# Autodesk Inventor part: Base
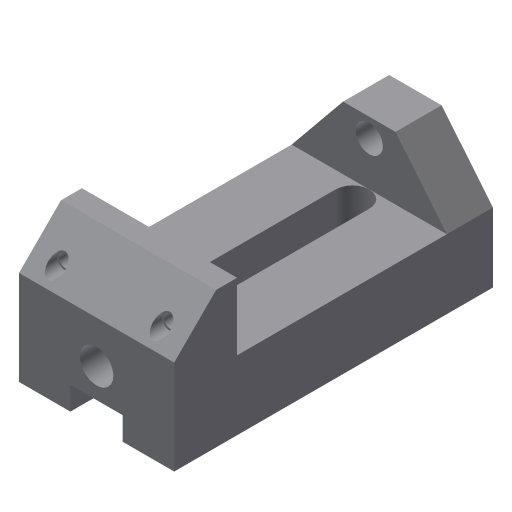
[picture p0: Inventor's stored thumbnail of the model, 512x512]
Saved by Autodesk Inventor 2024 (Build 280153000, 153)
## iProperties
Shininess: 77.0
Length Units: 11269
Angle Units: 11279
Time Units: 11290
Mass Units: 11283
Length Display Precision: 3
Angle Display Precision: 2
Created: 2002-02
Part Number: Base
Document SubType Name: Modeling
Designer: ***
Density: 1 g/cm^3
Material: Generic
Appearance: Default
Density: 0.0
Volumn: 0.0
Area: 0.0
PropertySet Name: Model Information
Control State: 0
Master: False
Checked Out: False
Author: ***
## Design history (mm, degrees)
sketch "Sketch2"
  geometry: L1 (-63.961, -4.254)-(-63.961, -37.254); L2 (-63.961, -37.254)-(88.039, -37.254); L3 (88.039, -37.254)-(88.039, 7.746); L4 (88.039, 7.746)-(68.039, 27.746); L5 (68.039, 27.746)-(58.039, 27.746); L6 (58.039, 27.746)-(58.039, -4.254); L7 (58.039, -4.254)-(-63.961, -4.254)
  constraints: 14 end point, 4 parallel, 1 perpendicular, 1 vertical
  dimensions: "d7" = 10 distance of L4.end L5.end; "d8" = 135 deg angle of L3 L4; "d9" = 33 distance of L1.start L1.end; "d10" = 152 distance of L1.end L2.end; "d11" = 65 distance between parallel lines of L5 L2; "d21" = 30 distance between parallel lines of L3 L6
extrude "Extrusion1" new body sketch "Sketch2" stored distance "d13" = 74; taper "d14" = 0 deg
sketch "Sketch3"
  geometry: L1 (0, 74)-(0, 0) reference; L2 (0, 0)-(-30, 24.5); L3 (-30, 24.5)-(-30, 49.5); L4 (-30, 49.5)-(0, 74); C1 r 6.5 at (-21, 37)
  constraints: 6 end point, 1 centre point, 1 equal length, 1 parallel
  dimensions: "d15" = 25 distance of L2.end L3.end; "d16" = 30 distance between parallel lines of L3 L1; "d17" = 13 diameter of C1; "d18" = 9 distance from line of L3 C1.centre
extrude "Extrusion2" join sketch "Sketch3" distance "d19" = 22; taper "d20" = 0 deg
sketch "Sketch4"
  geometry: L1 (0, 0)-(0, 74) reference; L2 (0, 0)-(45, 0) reference; C1 r 8 at (25, 37)
  constraints: 1 centre point
  dimensions: "d22" = 16 diameter of C1; "d23" = 25 distance from line of L1 C1.centre; "d24" = 37 distance from line of L2 C1.centre
extrude "Extrusion3" cut sketch "Sketch4" distance "d25" = 13; taper "d26" = 0 deg
sketch "Sketch5"
  geometry: L1 (45, 74)-(0, 74) reference; L2 (65, 0)-(65, 74) reference; 1 further point
  dimensions: "d27" = 12 distance from line of point (51, 62) L1; "d28" = 14 distance from line of L2 point (51, 62)
hole "Hole1" sketch "Sketch5" diameter "d29" = 6; stored, may be unused: countersink angle "d33" = 82 deg, drill point angle "d35" = 0 deg; dims "d30" = 6, "d31" = 8, "d32" = 10, "d34" = 30
mirror "Mirror1"
sketch "Sketch6"
  geometry: L1 (100, 0)-(100, 74) reference; L2 (100, 74)-(0, 74) reference; L3 (14, 45)-(92, 45); L4 (92, 29)-(14, 29); A1 r 8 centre (92, 37) between (92, 29) and (92, 45); A2 r 8 centre (14, 37) between (14, 45) and (14, 29)
  constraints: 4 end point, 4 point on circle, 4 tangent, 2 centre point, 1 horizontal, 1 parallel
  dimensions: "d36" = 8 radius of A2; "d37" = 78 distance of L4.start L4.end; "d38" = 8 distance from line of L1 A1.centre; "d39" = 37 distance from line of L2 A2.centre
extrude "Extrusion4" cut sketch "Sketch6" extent not by distance; stored distance "d40" = 13; taper "d41" = 0 deg
sketch "Sketch7"
  geometry: L1 (0, 49.5)-(11, 49.5); L2 (11, 49.5)-(11, 24.5); L3 (11, 24.5)-(0, 24.5); L4 (0, 24.5)-(0, 49.5); L5 (45, 74)-(0, 74) reference; L6 (0, 0)-(0, 74) reference
  constraints: 8 end point, 2 parallel, 1 collinear, 1 horizontal, 1 perpendicular
  dimensions: "d42" = 25 distance of L3.end L1.start; "d43" = 11 distance of L1.start L1.end; "d44" = 24.5 distance between parallel lines of L5 L1
extrude "Extrusion5" cut sketch "Sketch7" extent not by distance; stored distance "d45" = 13; taper "d46" = 0 deg
body "Solid1"
